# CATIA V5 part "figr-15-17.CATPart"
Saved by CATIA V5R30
Part number: Part1
Bounding box of the stored display mesh (mm): x -46.56 to 46.56, y -26.965 to 25.965, z 0 to 40
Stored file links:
  D:\PROJECTS\CATIA V56R 2020\Resources\Parts File\c15_catia_v5_6r2020_prt\figr-15-17.CATPart
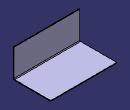
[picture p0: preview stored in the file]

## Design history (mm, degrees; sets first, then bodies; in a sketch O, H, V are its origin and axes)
SheetMetalParameters1: Thickness 1, BendRadius 1, KFactor 0.325257 {= log(min(100,max(20*SheetMetalParameters1.BendRadius,SheetMetalParameters1.Thickness)/SheetMetalParameters1.Thickness))/log(100)/2}, ReliefRadialLength 1, ReliefAxialLength 2, MinimumBendRadius 0
Body1 (main body)
  Sketch1 on xy-plane, origin (0, 0, 0), H (1, 0, 0), V (0, 1, 0)
    line L1 (-46.5596, 25.9646) -> (46.5596, 25.9646)
    line L2 (46.5596, 25.9646) -> (46.5596, -25.9646)
    line L3 (46.5596, -25.9646) -> (-46.5596, -25.9646)
    line L4 (-46.5596, -25.9646) -> (-46.5596, 25.9646)
    horizontal: L1 H, L3 H
    vertical: L2 V, L4 V
    symmetry: L1 L3 H, L4 L2 V
  Wall1: Thickness 1, Profile Sketch1
  d_NewWallOnEdge1: NewWallOnEdge_Edge edge [face of Wall1 | face of Wall1], NewWallOnEdge_Length 40, NewWallOnEdge_HeightLimitOffset 0, NewWallOnEdge_WidthOffset1 0, NewWallOnEdge_WidthOffset2 0, NewWallOnEdge_Angle 90, NewWallOnEdge_BendRadiusValue 1 {= SheetMetalParameters1.BendRadius}, NewWallOnEdge_BendTable SheetMetalParameters1, KFacteur 0.325257 {= log(min(100,max(20*d_NewWallOnEdge1.Radius,SheetMetalParameters1.Thickness)/SheetMetalParameters1.Thickness))/log(100)/2}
